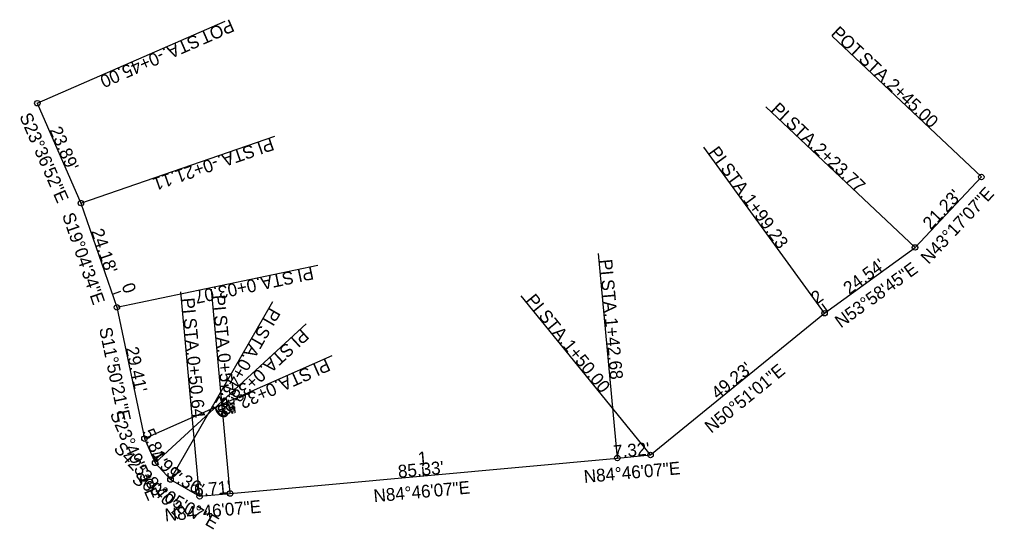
# Model space of a CAD drawing. Extents: x 2392769 to 2392983, y 185267 to 185379.
import ezdxf

# ---------------------------------------------------------------- set-up
doc = ezdxf.new("R2010")
doc.units = 0
for name, color, linetype in [('RW_X_CL', 7, 'Continuous'), ('RW_X_CL_100_Cardinal_Points', 7, 'Continuous'), ('RW_X_CL_100_Curve_Data', 7, 'Continuous'), ('RW_X_CL_100_Stations', 7, 'Continuous'), ('RW_X_Esmt_SH', 7, 'Continuous')]:
    doc.layers.add(name, color=color, linetype=linetype)

msp = doc.modelspace()

# ---------------------------------------------------------------- linework, layer by layer
at = {"layer": 'RW_X_CL_100_Cardinal_Points'}
for p, q in [((2392772.74, 185360.18), (2392813.97, 185378.2)), ((2392979.88, 185344.02), (2392947.13, 185374.88)), ((2392965.33, 185328.57), (2392932.57, 185359.42)), ((2392782.31, 185338.29), (2392824.84, 185352.99)), ((2392945.48, 185314.14), (2392919.02, 185350.54)), ((2392900.01, 185282.39), (2392895.91, 185327.2)), ((2392790.21, 185315.44), (2392834.26, 185324.67)), ((2392808.36, 185274), (2392804.25, 185318.81)), ((2392815.04, 185274.61), (2392810.94, 185319.42)), ((2392907.3, 185283.06), (2392878.89, 185317.96)), ((2392801.97, 185277.67), (2392824.41, 185316.68)), ((2392798.6, 185281.34), (2392831.7, 185311.82)), ((2392796.25, 185286.65), (2392837.41, 185304.84))]:
    msp.add_line(p, q, dxfattribs=at)
for centre in [(2392772.74, 185360.18), (2392979.88, 185344.02), (2392782.31, 185338.29), (2392965.33, 185328.57), (2392790.21, 185315.44), (2392945.48, 185314.14), (2392796.25, 185286.65), (2392907.3, 185283.06), (2392798.6, 185281.34), (2392900.01, 185282.39), (2392801.97, 185277.67), (2392815.04, 185274.61), (2392808.36, 185274)]:
    msp.add_circle(centre, 0.6, dxfattribs=at)
at = {"layer": 'RW_X_CL_100_Stations'}
for p, q in [((2392789.21, 185318.34), (2392791.1, 185318.99)), ((2392946.1, 185314.59), (2392944.93, 185316.21)), ((2392907.3, 185283.06), (2392906.55, 185283.99)), ((2392857.51, 185278.5), (2392857.33, 185280.49)), ((2392807.8, 185274.32), (2392808.4, 185275.36))]:
    msp.add_line(p, q, dxfattribs=at)
at = {"layer": 'RW_X_Esmt_SH'}
for p, q in [((2392772.74, 185360.18), (2392782.31, 185338.29)), ((2392965.33, 185328.57), (2392979.88, 185344.02)), ((2392782.31, 185338.29), (2392790.21, 185315.44)), ((2392945.48, 185314.14), (2392965.33, 185328.57)), ((2392790.21, 185315.44), (2392796.25, 185286.65)), ((2392907.3, 185283.06), (2392945.48, 185314.14)), ((2392796.25, 185286.65), (2392798.6, 185281.34)), ((2392798.6, 185281.34), (2392801.97, 185277.67)), ((2392815.04, 185274.61), (2392900.01, 185282.39)), ((2392900.01, 185282.39), (2392907.3, 185283.06)), ((2392801.97, 185277.67), (2392808.36, 185274)), ((2392808.36, 185274), (2392815.04, 185274.61))]:
    msp.add_line(p, q, dxfattribs=at)

# ---------------------------------------------------------------- texts
at = {"layer": 'RW_X_CL'}
for s, rotation, p in [('S23°36\'52"E', 293.6145, (2392768.75, 185357.33)), ('N43°17\'07"E', 46.7147, (2392968.31, 185324.73)), ('S19°04\'34"E', 289.0762, (2392778.15, 185335.63)), ('N53°58\'45"E', 36.0208, (2392949.04, 185310.79)), ('S11°50\'21"E', 281.839, (2392786.29, 185310.77)), ('N50°51\'01"E', 39.1496, (2392920.61, 185287.7)), ('S23°49\'51"E', 293.8308, (2392788.61, 185292.06)), ('S42°38\'40"E', 312.6444, (2392789.34, 185284.3)), ('N84°46\'07"E', 5.2313, (2392892.78, 185276.91)), ('S60°05\'07"E', 330.0853, (2392793.29, 185277.13)), ('N84°46\'07"E', 5.2313, (2392846.65, 185272.68)), ('N84°46\'07"E', 5.2313, (2392800.82, 185268.49))]:
    msp.add_text(s, height=2.8, rotation=rotation, dxfattribs=at).set_placement(p)
at = {"layer": 'RW_X_CL_100_Cardinal_Points'}
for s, rotation, p in [('POT', 203.6145, (2392815.13, 185378.66)), (' STA. ', 203.6145, (2392808.53, 185375.78)), ('POT', 316.7147, (2392946.74, 185375.3)), ('-0+45.00', 203.6145, (2392799.87, 185371.99)), (' STA. ', 316.7147, (2392951.99, 185370.36)), ('2+45.00', 316.7147, (2392958.87, 185363.88)), ('PI', 316.7147, (2392933.52, 185358.58)), (' STA. ', 316.7147, (2392935.99, 185356.26)), ('PI', 199.0762, (2392824.04, 185352.67)), (' STA. ', 199.0762, (2392820.84, 185351.57)), ('PI', 306.0208, (2392919.88, 185349.42)), ('2+23.77', 316.7147, (2392942.87, 185349.78)), ('-0+21.11', 199.0762, (2392811.9, 185348.48)), (' STA. ', 306.0208, (2392921.88, 185346.67)), ('1+99.23', 306.0208, (2392927.44, 185339.03)), ('PI', 191.839, (2392833.02, 185324.37)), ('PI', 275.2313, (2392896.08, 185325.86)), (' STA. ', 191.839, (2392829.7, 185323.67)), ('0+03.07', 191.839, (2392820.45, 185321.73)), (' STA. ', 275.2313, (2392896.39, 185322.48)), ('PI', 275.2313, (2392811.11, 185318.05)), ('PI', 309.1496, (2392879.77, 185316.94)), ('PI', 275.2313, (2392804.42, 185317.41)), (' STA. ', 275.2313, (2392811.42, 185314.67)), ('PI', 240.0853, (2392823.82, 185315.55)), (' STA. ', 309.1496, (2392881.91, 185314.31)), (' STA. ', 275.2313, (2392804.73, 185314.03)), (' STA. ', 240.0853, (2392822.13, 185312.61)), ('1+42.68', 275.2313, (2392897.25, 185313.07)), ('PI', 222.6444, (2392830.72, 185310.87)), (' STA. ', 222.6444, (2392828.22, 185308.57)), ('1+50.00', 309.1496, (2392887.88, 185306.98)), ('0+57.35', 275.2313, (2392812.28, 185305.26)), ('0+50.64', 275.2313, (2392805.59, 185304.62)), ('0+43.27', 240.0853, (2392817.41, 185304.42)), ('PI', 203.8308, (2392836.19, 185304.25)), ('0+38.29', 222.6444, (2392821.27, 185302.17)), (' STA. ', 203.8308, (2392833.09, 185302.88)), ('0+32.48', 203.8308, (2392824.44, 185299.06))]:
    msp.add_text(s, height=2.8, rotation=rotation, dxfattribs=at).set_placement(p)
at = {"layer": 'RW_X_CL_100_Curve_Data'}
for s, rotation, p in [("23.89'", 293.6145, (2392775.34, 185354.35)), ("21.23'", 46.7147, (2392968.76, 185332.28)), ("24.18'", 289.0762, (2392784.49, 185332.13)), ("24.54'", 36.0208, (2392950.88, 185318.12)), ("29.41'", 281.839, (2392792.13, 185306.5)), ("49.23'", 39.1496, (2392922.05, 185295.12)), ("5.81'", 293.8308, (2392795.66, 185288.08)), ("7.32'", 5.2313, (2392899.23, 185282.36)), ("4.99'", 312.6444, (2392797.3, 185282.8)), ("85.33'", 5.2313, (2392851.99, 185278.04)), ("7.36'", 330.0853, (2392801.33, 185278.09)), ("6.71'", 5.2313, (2392807.27, 185273.94))]:
    msp.add_text(s, height=2.8, rotation=rotation, dxfattribs=at).set_placement(p)
at = {"layer": 'RW_X_CL_100_Stations'}
for s, rotation, p in [('0', 289.0762, (2392791.21, 185320.21)), ('2', 36.0208, (2392943.79, 185316)), ('1', 5.2313, (2392856.37, 185280.91))]:
    msp.add_text(s, height=2.8, rotation=rotation, dxfattribs=at).set_placement(p)

doc.saveas('drawing.dxf')
